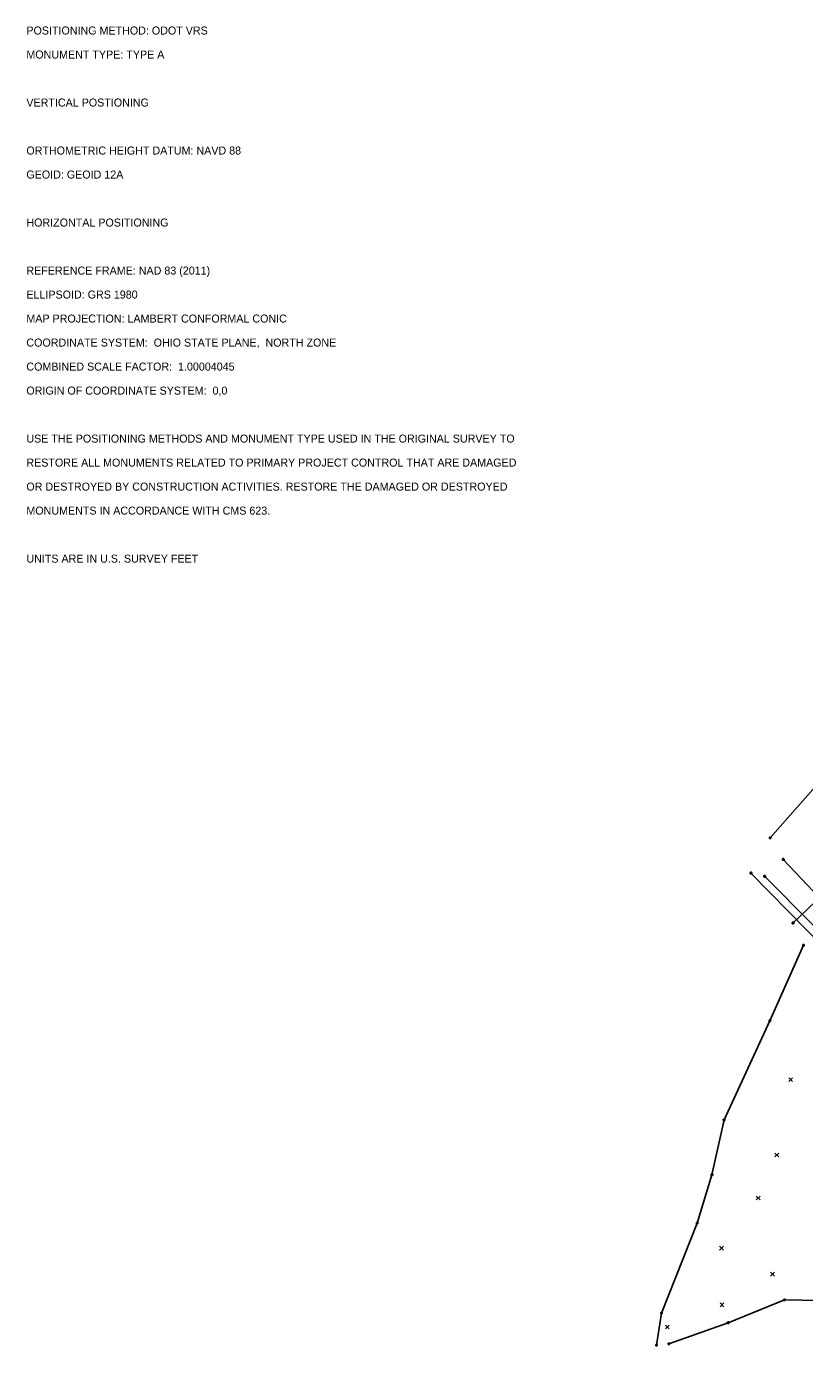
# Model space of a CAD drawing. Extents: x 2331247 to 2333939, y 279314 to 282014.
# Drawn here: x 2332076.4 to 2332348.6, y 279981.7 to 280443.7 of the extents above; entities that cross this region are included whole.
import ezdxf

# ---------------------------------------------------------------- set-up
doc = ezdxf.new("R2010")
doc.units = 0
for name, color, linetype in [('DR_X_Storm_Sewer', 7, 'Continuous'), ('PV_X_Driveway', 7, 'Continuous'), ('RD_X_Fence', 7, 'Continuous'), ('Stream 1', 7, 'Continuous'), ('SV_X_Break_Lines', 7, 'Continuous'), ('SV_X_Random_Point', 7, 'Continuous'), ('SV_X_Text', 7, 'Continuous')]:
    doc.layers.add(name, color=color, linetype=linetype)

msp = doc.modelspace()

# ---------------------------------------------------------------- linework, layer by layer
at = {"layer": 'DR_X_Storm_Sewer'}
msp.add_lwpolyline([(2332357.87, 280142.51), (2332344.55, 280129.9)], dxfattribs=at)
at = {"layer": 'PV_X_Driveway'}
msp.add_lwpolyline([(2332334.66, 280146.26), (2332368.53, 280112.11), (2332376.7, 280119.03), (2332355.89, 280136.6), (2332341.2, 280152.16)], dxfattribs=at)
at = {"layer": 'RD_X_Fence'}
msp.add_lwpolyline([(2332329.87, 280147.38), (2332388.96, 280087.12), (2332443.79, 280029.59), (2332520.53, 280051.39), (2332545.34, 280054.73), (2332609.48, 280056.66), (2332637.98, 280057.25), (2332654.75, 280058.93), (2332722.3, 280080.02), (2332912.53, 280139.11)], dxfattribs=at)
at = {"layer": 'Stream 1'}
for p, q in [((2332336.11, 280159.69), (2332337.11, 280159.69)), ((2332336.61, 280160.19), (2332336.61, 280159.19)), ((2332336.61, 280159.69), (2332336.61, 280159.69)), ((2332340.7, 280152.16), (2332341.7, 280152.16)), ((2332341.2, 280152.66), (2332341.2, 280151.66)), ((2332341.2, 280152.16), (2332341.2, 280152.16)), ((2332329.37, 280147.38), (2332330.37, 280147.38)), ((2332329.87, 280147.88), (2332329.87, 280146.88)), ((2332329.87, 280147.38), (2332329.87, 280147.38)), ((2332334.16, 280146.26), (2332335.16, 280146.26)), ((2332334.66, 280146.76), (2332334.66, 280145.76)), ((2332334.66, 280146.26), (2332334.66, 280146.26)), ((2332344.05, 280129.9), (2332345.05, 280129.9)), ((2332344.55, 280130.4), (2332344.55, 280129.4)), ((2332344.55, 280129.9), (2332344.55, 280129.9)), ((2332347.78, 280122.1), (2332348.78, 280122.1)), ((2332348.28, 280122.6), (2332348.28, 280121.6)), ((2332348.28, 280122.1), (2332348.28, 280122.1)), ((2332335.98, 280095.72), (2332336.98, 280095.72)), ((2332336.48, 280096.22), (2332336.48, 280095.22)), ((2332336.48, 280095.72), (2332336.48, 280095.72)), ((2332319.97, 280060.99), (2332320.97, 280060.99)), ((2332320.47, 280061.49), (2332320.47, 280060.49)), ((2332320.47, 280060.99), (2332320.47, 280060.99)), ((2332315.73, 280041.83), (2332316.73, 280041.83)), ((2332316.23, 280042.33), (2332316.23, 280041.33)), ((2332316.23, 280041.83), (2332316.23, 280041.83)), ((2332310.58, 280024.88), (2332311.58, 280024.88)), ((2332311.08, 280025.38), (2332311.08, 280024.38)), ((2332311.08, 280024.88), (2332311.08, 280024.88)), ((2332341.12, 279998.04), (2332342.12, 279998.04)), ((2332341.62, 279998.54), (2332341.62, 279997.54)), ((2332341.62, 279998.04), (2332341.62, 279998.04)), ((2332298.07, 279993.36), (2332299.07, 279993.36)), ((2332298.57, 279993.86), (2332298.57, 279992.86)), ((2332298.57, 279993.36), (2332298.57, 279993.36)), ((2332321.35, 279990.04), (2332322.35, 279990.04)), ((2332321.85, 279990.54), (2332321.85, 279989.54)), ((2332321.85, 279990.04), (2332321.85, 279990.04)), ((2332296.32, 279982.18), (2332297.32, 279982.18)), ((2332296.82, 279982.68), (2332296.82, 279981.68)), ((2332296.82, 279982.18), (2332296.82, 279982.18)), ((2332300.63, 279982.66), (2332301.63, 279982.66)), ((2332301.13, 279983.16), (2332301.13, 279982.16)), ((2332301.13, 279982.66), (2332301.13, 279982.66))]:
    msp.add_line(p, q, dxfattribs=at)
at = {"layer": 'SV_X_Break_Lines'}
for points in [[(2332419.17, 280258.97), (2332407.22, 280243.15), (2332393.46, 280225.83), (2332381.83, 280214.45), (2332368.29, 280197.28), (2332353.31, 280178.63), (2332336.61, 280159.69)], [(2332348.28, 280122.1), (2332336.48, 280095.72), (2332320.47, 280060.99), (2332316.23, 280041.83), (2332311.08, 280024.88), (2332298.57, 279993.36), (2332296.82, 279982.18)], [(2332637.89, 280055.68), (2332619.53, 280052.31), (2332597.02, 280049.35), (2332579.9, 280046.98), (2332561.44, 280045.35), (2332538.2, 280046.05), (2332519.12, 280045.93), (2332504.12, 280046.01), (2332488.77, 280042.65), (2332447.87, 280018.78), (2332423.37, 280008.83), (2332404.51, 280011.61), (2332392.96, 280006.54), (2332376.59, 280000.88), (2332366.07, 279997.58), (2332341.62, 279998.04), (2332321.85, 279990.04), (2332301.13, 279982.66)]]:
    msp.add_lwpolyline(points, dxfattribs=at)
at = {"layer": 'SV_X_Random_Point'}
for p, q in [((2332343.07, 280074.41), (2332344.4, 280075.75)), ((2332343.07, 280075.75), (2332344.4, 280074.41)), ((2332338.27, 280048.05), (2332339.61, 280049.38)), ((2332338.27, 280049.38), (2332339.61, 280048.05)), ((2332331.72, 280033.03), (2332333.06, 280034.37)), ((2332331.72, 280034.37), (2332333.06, 280033.03)), ((2332318.92, 280015.44), (2332320.25, 280016.78)), ((2332318.92, 280016.78), (2332320.25, 280015.44)), ((2332336.76, 280006.35), (2332338.09, 280007.69)), ((2332336.76, 280007.69), (2332338.09, 280006.35)), ((2332319.11, 279995.61), (2332320.44, 279996.95)), ((2332319.11, 279996.95), (2332320.44, 279995.61)), ((2332299.95, 279987.9), (2332301.28, 279989.23)), ((2332299.95, 279989.23), (2332301.28, 279987.9))]:
    msp.add_line(p, q, dxfattribs=at)

# ---------------------------------------------------------------- texts
at = {"layer": 'SV_X_Text'}
for s, p in [('POSITIONING METHOD: ODOT VRS', (2332076.42, 280440.82)), ('MONUMENT TYPE: TYPE A', (2332076.42, 280432.42)), ('VERTICAL POSTIONING', (2332076.42, 280415.62)), ('ORTHOMETRIC HEIGHT DATUM: NAVD 88', (2332076.42, 280398.82)), ('GEOID: GEOID 12A', (2332076.42, 280390.42)), ('HORIZONTAL POSITIONING', (2332076.42, 280373.62)), ('REFERENCE FRAME: NAD 83 (2011)', (2332076.42, 280356.82)), ('ELLIPSOID: GRS 1980', (2332076.42, 280348.42)), ('MAP PROJECTION: LAMBERT CONFORMAL CONIC', (2332076.42, 280340.02)), ('COORDINATE SYSTEM:  OHIO STATE PLANE,  NORTH ZONE', (2332076.42, 280331.62)), ('COMBINED SCALE FACTOR:  1.00004045', (2332076.42, 280323.22)), ('ORIGIN OF COORDINATE SYSTEM:  0,0', (2332076.42, 280314.82)), ('USE THE POSITIONING METHODS AND MONUMENT TYPE USED IN THE ORIGINAL SURVEY TO', (2332076.42, 280298.02)), ('RESTORE ALL MONUMENTS RELATED TO PRIMARY PROJECT CONTROL THAT ARE DAMAGED', (2332076.42, 280289.62)), ('OR DESTROYED BY CONSTRUCTION ACTIVITIES. RESTORE THE DAMAGED OR DESTROYED', (2332076.42, 280281.22)), ('MONUMENTS IN ACCORDANCE WITH CMS 623.', (2332076.42, 280272.82)), ('UNITS ARE IN U.S. SURVEY FEET', (2332076.42, 280256.02))]:
    msp.add_text(s, height=2.8, dxfattribs=at).set_placement(p)

doc.saveas('drawing.dxf')
